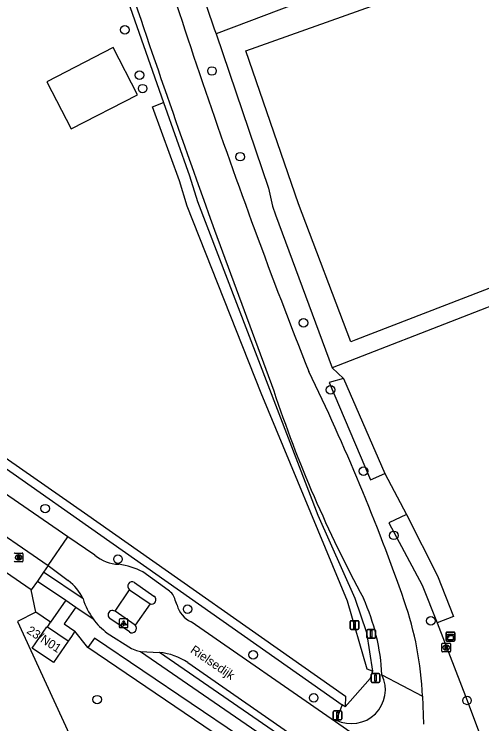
# Model space of a CAD drawing. Extents: x 163863 to 164644, y 379566 to 382155.
# Drawn here: x 164404.5 to 164457.9, y 381693.6 to 381774.7 of the extents above; entities that cross this region are included whole.
import ezdxf

# ---------------------------------------------------------------- set-up
doc = ezdxf.new("R2010")
doc.units = 0
for name, color, linetype in [('IMGEO_Afsluitpaal', 7, 'Continuous'), ('IMGEO_Boom', 7, 'Continuous'), ('IMGEO_Brandkraan', 7, 'Continuous'), ('IMGEO_Erf', 7, 'Continuous'), ('IMGEO_Grasland_agrarisch', 7, 'Continuous'), ('IMGEO_Groenvoorziening', 7, 'Continuous'), ('IMGEO_Hek', 7, 'Continuous'), ('IMGEO_Kast', 7, 'Continuous'), ('IMGEO_Lichtpunt', 7, 'Continuous'), ('IMGEO_Openbare_ruimte_label', 7, 'Continuous'), ('IMGEO_Pand', 7, 'Continuous'), ('IMGEO_Pand_nummerreeks', 7, 'Continuous'), ('IMGEO_Parkeervlak_open', 7, 'Continuous'), ('IMGEO_Rijbaan_lokaal_gesloten', 7, 'Continuous'), ('IMGEO_Rijbaan_lokaal_halfverhard', 7, 'Continuous'), ('IMGEO_Rijbaan_lokaal_open', 7, 'Continuous'), ('IMGEO_Rioolput', 7, 'Continuous'), ('IMGEO_Verkeersbordpaal', 7, 'Continuous'), ('IMGEO_Voetpad_open', 7, 'Continuous'), ('IMGEO_Waterloop', 7, 'Continuous')]:
    doc.layers.add(name, color=color, linetype=linetype)

msp = doc.modelspace()

# ---------------------------------------------------------------- linework, layer by layer
at = {"layer": 'IMGEO_Afsluitpaal'}
for p, q in [((164444.797, 381703.434), (164444.797, 381704.234)), ((164444.797, 381704.234), (164444.797, 381703.434)), ((164444.897, 381704.334), (164445.687, 381704.334)), ((164445.687, 381704.334), (164444.897, 381704.334)), ((164445.787, 381704.234), (164445.787, 381703.434)), ((164445.787, 381703.434), (164445.787, 381704.234)), ((164445.687, 381703.334), (164444.897, 381703.334)), ((164444.897, 381703.334), (164445.687, 381703.334)), ((164445.274, 381698.398), (164445.274, 381699.198)), ((164445.274, 381699.198), (164445.274, 381698.398)), ((164445.374, 381699.298), (164446.164, 381699.298)), ((164446.164, 381699.298), (164445.374, 381699.298)), ((164446.264, 381699.198), (164446.264, 381698.398)), ((164446.264, 381698.398), (164446.264, 381699.198)), ((164446.164, 381698.298), (164445.374, 381698.298)), ((164445.374, 381698.298), (164446.164, 381698.298)), ((164440.936, 381694.125), (164440.936, 381694.925)), ((164440.936, 381694.925), (164440.936, 381694.125)), ((164441.036, 381695.025), (164441.826, 381695.025)), ((164441.826, 381695.025), (164441.036, 381695.025)), ((164441.926, 381694.925), (164441.926, 381694.125)), ((164441.926, 381694.125), (164441.926, 381694.925)), ((164441.826, 381694.025), (164441.036, 381694.025)), ((164441.036, 381694.025), (164441.826, 381694.025))]:
    msp.add_line(p, q, dxfattribs=at)
for points in [[(164445.217, 381704.209), (164445.367, 381704.209), (164445.367, 381703.459), (164445.217, 381703.459), (164445.217, 381704.209)], [(164445.694, 381699.173), (164445.844, 381699.173), (164445.844, 381698.423), (164445.694, 381698.423), (164445.694, 381699.173)], [(164441.356, 381694.9), (164441.506, 381694.9), (164441.506, 381694.15), (164441.356, 381694.15), (164441.356, 381694.9)]]:
    msp.add_lwpolyline(points, dxfattribs=at)
for centre, start, end in [((164444.897, 381704.234), 90, 180), ((164444.897, 381704.234), 90, 180), ((164445.687, 381704.234), 0, 90), ((164445.687, 381704.234), 360, 90), ((164444.897, 381703.434), 180, 270), ((164444.897, 381703.434), 180, 270), ((164445.687, 381703.434), 270, 0), ((164445.687, 381703.434), 270, 0), ((164445.374, 381699.198), 90, 180), ((164445.374, 381699.198), 90, 180), ((164446.164, 381699.198), 0, 90), ((164446.164, 381699.198), 360, 90), ((164445.374, 381698.398), 180, 270), ((164445.374, 381698.398), 180, 270), ((164446.164, 381698.398), 270, 0), ((164446.164, 381698.398), 270, 0), ((164441.036, 381694.925), 90, 180), ((164441.036, 381694.925), 90, 180), ((164441.826, 381694.925), 0, 90), ((164441.826, 381694.925), 360, 90), ((164441.036, 381694.125), 180, 270), ((164441.036, 381694.125), 180, 270), ((164441.826, 381694.125), 270, 0), ((164441.826, 381694.125), 270, 0)]:
    msp.add_arc(centre, 0.1, start, end, dxfattribs=at)
at = {"layer": 'IMGEO_Boom'}
for centre in [(164417.112, 381772.922), (164418.805, 381767.744), (164427.081, 381768.213), (164419.153, 381766.193), (164430.293, 381758.411), (164437.543, 381739.415), (164440.63, 381731.745), (164444.404, 381722.448), (164407.999, 381718.165), (164447.885, 381715.108), (164416.332, 381712.377), (164424.297, 381706.667), (164452.106, 381705.325), (164431.799, 381701.437), (164413.958, 381696.321), (164438.709, 381696.515), (164456.242, 381696.233)]:
    msp.add_circle(centre, 0.489, dxfattribs=at)
at = {"layer": 'IMGEO_Brandkraan'}
for p, q in [((164404.539, 381713.084), (164405.391, 381713.084)), ((164405.465, 381713.01), (164405.465, 381712.158)), ((164404.975, 381712.304), (164404.95, 381712.304)), ((164404.952, 381712.864), (164404.977, 381712.864)), ((164405.391, 381712.084), (164404.539, 381712.084))]:
    msp.add_line(p, q, dxfattribs=at)
for points in [[(164404.539, 381713.084), (164405.391, 381713.084)], [(164405.465, 381713.01), (164405.465, 381712.158)], [(164404.812, 381712.784), (164404.812, 381712.384), (164405.025, 381712.384)], [(164405.043, 381712.784), (164404.812, 381712.784)], [(164404.991, 381712.703), (164404.937, 381712.703), (164404.937, 381712.627)], [(164404.937, 381712.627), (164404.99, 381712.627)], [(164404.999, 381712.551), (164404.937, 381712.551), (164404.937, 381712.47)], [(164404.937, 381712.47), (164404.999, 381712.47)], [(164405.391, 381712.084), (164404.539, 381712.084)]]:
    msp.add_lwpolyline(points, dxfattribs=at)
for centre, radius, start, end in [((164404.541, 381713.008), 0.0765, 91.55205, 178.44795), ((164404.541, 381713.008), 0.0765, 91.55205, 178.44795), ((164405.389, 381713.008), 0.0765, 1.55205, 88.44795), ((164405.389, 381713.008), 0.0765, 1.55205, 88.44795), ((164404.541, 381712.16), 0.0765, 181.55205, 268.44795), ((164404.541, 381712.16), 0.0765, 181.55205, 268.44795), ((164404.992, 381712.665), 0.0379, 267.82845, 90.93552), ((164405, 381712.51), 0.0404, 269.87594, 90.50774), ((164405.031, 381712.635), 0.251, 268.66757, 293.53466), ((164405.047, 381712.639), 0.145, 59.4692, 91.53667), ((164405.072, 381712.686), 0.0922, 285.51372, 58.15012), ((164405.077, 381712.494), 0.105, 301.31148, 78.98903), ((164405.389, 381712.16), 0.0765, 271.55205, 358.44795), ((164405.389, 381712.16), 0.0765, 271.55205, 358.44795)]:
    msp.add_arc(centre, radius, start, end, dxfattribs=at)
for centre, major_axis, ratio, start_param, end_param in [((164404.951, 381712.584), (-0.387, 0.002), 0.722429, 4.712389, 7.853982), ((164404.976, 381712.584), (-0.39, 0.002), 0.717154, 1.570796, 4.712389)]:
    msp.add_ellipse(centre, major_axis=major_axis, ratio=ratio, start_param=start_param, end_param=end_param, dxfattribs=at)
at = {"layer": 'IMGEO_Erf'}
msp.add_lwpolyline([(164580.013, 381810.414), (164581.346, 381805.246), (164575.754, 381802.969), (164541.615, 381789.068), (164545.187, 381772.796), (164538.087, 381770.586), (164534.647, 381771.115), (164468.83, 381745.172), (164457.1, 381740.602), (164440.833, 381734.263)], dxfattribs=at)
at = {"layer": 'IMGEO_Grasland_agrarisch'}
for points in [[(164600.098, 381839.014), (164585.232, 381833.12), (164548.829, 381818.751), (164518.638, 381806.884), (164490.643, 381796.474), (164469.448, 381788.316), (164427.546, 381772.442)], [(164443.539, 381737.474), (164442.939, 381737.247), (164436.966, 381753.014), (164430.965, 381770.512), (164456.78, 381779.759), (164478.348, 381787.868), (164505.546, 381798.321), (164526.662, 381806.514), (164530.385, 381805.09), (164531.541, 381804.475), (164532.487, 381803.404), (164538.297, 381784.937), (164539.439, 381780.675), (164539.19, 381777.888), (164537.822, 381775.597), (164535.89, 381774.091), (164533.834, 381772.761), (164490.018, 381755.433), (164443.539, 381737.474)], [(164418.253, 381799.855), (164427.349, 381773.022), (164427.546, 381772.442)]]:
    msp.add_lwpolyline(points, dxfattribs=at)
at = {"layer": 'IMGEO_Groenvoorziening'}
for points in [[(164416.201, 381779.849), (164421.545, 381764.607)], [(164427.546, 381772.442), (164433.526, 381754.803), (164433.997, 381752.734), (164434.331, 381751.745), (164440.833, 381734.263)], [(164440.833, 381734.263), (164442.117, 381733.052)], [(164446.861, 381722.173), (164449.308, 381717.487)], [(164406.925, 381706.323), (164406.418, 381708.86)], [(164406.925, 381706.323), (164404.83, 381705.266), (164418.395, 381675.757)], [(164408.629, 381705.166), (164406.925, 381706.323)], [(164452.839, 381705.104), (164456.242, 381696.233), (164460.508, 381684.892), (164470.413, 381677.426)], [(164412.893, 381702.27), (164411.398, 381704.132)], [(164445.453, 381699.564), (164445.182, 381698.732), (164442.313, 381695.498)], [(164441.971, 381695.738), (164441.297, 381693.99)]]:
    msp.add_lwpolyline(points, dxfattribs=at)
at = {"layer": 'IMGEO_Hek'}
for points in [[(164468.83, 381745.172), (164457.1, 381740.602)], [(164457.1, 381740.602), (164440.833, 381734.263)]]:
    msp.add_lwpolyline(points, dxfattribs=at)
at = {"layer": 'IMGEO_Kast'}
for p, q in [((164453.925, 381704.024), (164454.766, 381704.024)), ((164454.766, 381704.024), (164453.925, 381704.024)), ((164453.85, 381703.099), (164453.85, 381703.94)), ((164453.85, 381703.94), (164453.85, 381703.099)), ((164454.85, 381703.949), (164454.85, 381703.108)), ((164454.85, 381703.108), (164454.85, 381703.949)), ((164454.775, 381703.024), (164453.934, 381703.024)), ((164453.934, 381703.024), (164454.775, 381703.024))]:
    msp.add_line(p, q, dxfattribs=at)
for points in [[(164454.045, 381703.814), (164454.645, 381703.814), (164454.645, 381703.729), (164454.045, 381703.729), (164454.045, 381703.814)], [(164454.045, 381703.639), (164454.645, 381703.639), (164454.645, 381703.15), (164454.045, 381703.15), (164454.045, 381703.639)]]:
    msp.add_lwpolyline(points, dxfattribs=at)
msp.add_circle((164454.129, 381703.488), 0.0377, dxfattribs=at)
for centre, start, end in [((164453.928, 381703.946), 92.4484, 184.28452), ((164453.928, 381703.946), 92.4484, 184.28452), ((164454.772, 381703.946), 2.4484, 94.28452), ((164454.772, 381703.946), 2.4484, 94.28452), ((164453.928, 381703.102), 182.4484, 274.28452), ((164453.928, 381703.102), 182.4484, 274.28452), ((164454.772, 381703.102), 272.4484, 4.28452), ((164454.772, 381703.102), 272.4484, 4.28452)]:
    msp.add_arc(centre, 0.0779, start, end, dxfattribs=at)
at = {"layer": 'IMGEO_Lichtpunt'}
for p, q in [((164416.479, 381705.452), (164416.479, 381704.645)), ((164416.479, 381705.452), (164416.479, 381704.645)), ((164417.381, 381705.547), (164416.573, 381705.547)), ((164417.381, 381705.547), (164416.573, 381705.547)), ((164417.475, 381704.645), (164417.475, 381705.452)), ((164417.475, 381704.645), (164417.475, 381705.452)), ((164416.573, 381704.551), (164417.381, 381704.551)), ((164416.573, 381704.551), (164417.381, 381704.551))]:
    msp.add_line(p, q, dxfattribs=at)
for points in [[(164416.853, 381705.116), (164416.892, 381705.088), (164416.704, 381704.826), (164416.666, 381704.853), (164416.853, 381705.116)], [(164416.955, 381705.068), (164417.002, 381705.068), (164417.002, 381704.746), (164416.955, 381704.746), (164416.955, 381705.068)], [(164417.065, 381705.088), (164417.103, 381705.115), (164417.29, 381704.853), (164417.251, 381704.825), (164417.065, 381705.088)]]:
    msp.add_lwpolyline(points, dxfattribs=at)
msp.add_circle((164416.978, 381705.25), 0.0994, dxfattribs=at)
for centre, start, end in [((164416.573, 381705.452), 90, 180), ((164416.573, 381705.452), 90, 180), ((164417.381, 381705.452), 0, 90), ((164417.381, 381705.452), 0, 90), ((164416.573, 381704.645), 180, 270), ((164416.573, 381704.645), 180, 270), ((164417.381, 381704.645), 270, 0), ((164417.381, 381704.645), 270, 360)]:
    msp.add_arc(centre, 0.0946, start, end, dxfattribs=at)
at = {"layer": 'IMGEO_Pand'}
for points in [[(164408.191, 381766.99), (164410.97, 381761.583), (164418.566, 381765.488), (164415.787, 381770.894), (164408.191, 381766.99)], [(164410.636, 381702.998), (164408.971, 381700.556), (164406.531, 381702.22), (164408.196, 381704.662), (164408.255, 381704.621)], [(164410.636, 381702.998), (164408.255, 381704.621)]]:
    msp.add_lwpolyline(points, dxfattribs=at)
at = {"layer": 'IMGEO_Parkeervlak_open'}
for points in [[(164406.418, 381708.86), (164381.892, 381725.724), (164366.579, 381736.251)], [(164408.346, 381711.663), (164407.816, 381710.901)], [(164407.122, 381709.878), (164406.418, 381708.86)]]:
    msp.add_lwpolyline(points, dxfattribs=at)
at = {"layer": 'IMGEO_Rijbaan_lokaal_gesloten'}
for points in [[(164324.768, 381769.068), (164352.536, 381750), (164383.72, 381728.586), (164408.346, 381711.663)], [(164410.608, 381714.952), (164385.909, 381731.949), (164382.848, 381734.057)], [(164408.346, 381711.663), (164410.608, 381714.952)], [(164413.701, 381712.823), (164410.608, 381714.952)], [(164408.346, 381711.663), (164410.627, 381709.931)], [(164422.052, 381708.834), (164419.173, 381710.931)], [(164418.21, 381709.722), (164420.438, 381708.15)], [(164423.088, 381707.112), (164422.863, 381707.691)], [(164417.638, 381704.058), (164415.41, 381705.593)], [(164441.191, 381693.787), (164424.684, 381705.234)], [(164415.108, 381703.926), (164417.871, 381702.173), (164418.468, 381701.923), (164418.924, 381701.808)], [(164418.924, 381701.808), (164421.084, 381701.704)], [(164424.306, 381700.566), (164445.106, 381686.132)], [(164455.774, 381683.629), (164441.191, 381693.787)]]:
    msp.add_lwpolyline(points, dxfattribs=at)
for centre, radius, start, end in [((164416.629, 381716.454), 4.664, 231.11326, 267.44259), ((164415.29, 381703.367), 8.502, 62.8239, 82.35428), ((164407.619, 381705.714), 5.18, 24.37833, 54.497), ((164417.936, 381709.302), 0.501, 56.8492, 236.49953), ((164420.17, 381707.732), 0.497, 249.35691, 57.35736), ((164421.259, 381707.412), 1.628, 9.85687, 60.85729), ((164420.524, 381710.505), 8.606, 197.95255, 215.15765), ((164415.7, 381706.008), 0.506, 54.56794, 235.06763), ((164425.923, 381707.905), 2.944, 195.61576, 245.10268), ((164419.638, 381710.068), 7.632, 216.30636, 233.58763), ((164417.937, 381704.467), 0.507, 233.82818, 46.35763), ((164420.507, 381694.941), 6.788, 55.9678, 85.12609)]:
    msp.add_arc(centre, radius, start, end, dxfattribs=at)
at = {"layer": 'IMGEO_Rijbaan_lokaal_halfverhard'}
msp.add_lwpolyline([(164427.37, 381750), (164434.141, 381731.625)], dxfattribs=at)
for centre, radius, start, end in [((165106.27, 381998.229), 718.528, 197.518249, 200.210398), ((165706.499, 382210.947), 1359.648, 198.437671, 199.817128), ((165106.385, 381998.122), 718.598, 200.199284, 201.576641), ((164221.983, 381628.478), 240.478, 19.20953, 25.99054), ((164576.493, 381779.107), 150.062, 198.44616, 208.32428), ((164422.47, 381697.97), 24.074, 2.81472, 24.38158), ((164413.003, 381695.065), 38.185, 2.46924, 19.16559)]:
    msp.add_arc(centre, radius, start, end, dxfattribs=at)
at = {"layer": 'IMGEO_Rijbaan_lokaal_open'}
for points in [[(164415.993, 381706.42), (164417.659, 381708.884)], [(164417.659, 381708.884), (164419.995, 381707.267)], [(164419.995, 381707.267), (164418.287, 381704.834)], [(164418.287, 381704.834), (164415.993, 381706.42)], [(164446.515, 381699.152), (164451.153, 381696.71)], [(164451.153, 381696.71), (164451.272, 381693.533)], [(164441.297, 381693.99), (164441.191, 381693.787)]]:
    msp.add_lwpolyline(points, dxfattribs=at)
msp.add_arc((164443.036, 381697.45), 3.873, 243.31119, 26.07059, dxfattribs=at)
at = {"layer": 'IMGEO_Rioolput'}
for p, q in [((164453.363, 381701.847), (164453.363, 381702.699)), ((164453.438, 381702.773), (164454.29, 381702.773)), ((164453.851, 381702.553), (164453.876, 381702.553)), ((164454.364, 381702.699), (164454.364, 381701.847)), ((164454.29, 381701.773), (164453.438, 381701.773)), ((164453.874, 381701.993), (164453.849, 381701.993))]:
    msp.add_line(p, q, dxfattribs=at)
for points in [[(164453.363, 381701.847), (164453.363, 381702.699)], [(164453.438, 381702.773), (164454.29, 381702.773)], [(164453.952, 381702.471), (164453.7, 381702.473), (164453.7, 381702.073)], [(164453.878, 381702.392), (164453.824, 381702.392), (164453.824, 381702.311)], [(164454.364, 381702.699), (164454.364, 381701.847)], [(164454.29, 381701.773), (164453.438, 381701.773)], [(164453.7, 381702.073), (164453.824, 381702.073), (164453.824, 381702.235), (164453.835, 381702.235)], [(164453.824, 381702.311), (164453.876, 381702.311)], [(164453.882, 381702.206), (164453.953, 381702.073), (164454.093, 381702.073), (164454.028, 381702.199)]]:
    msp.add_lwpolyline(points, dxfattribs=at)
for centre, radius, start, end in [((164453.44, 381702.697), 0.0765, 91.55205, 178.44795), ((164453.44, 381702.697), 0.0765, 91.55205, 178.44795), ((164453.884, 381702.296), 0.0964, 77.00612, 93.18647), ((164453.898, 381702.353), 0.0378, 276.66336, 79.67722), ((164453.951, 381702.361), 0.109, 350.36119, 89.41601), ((164454.288, 381702.697), 0.0765, 1.55205, 88.44795), ((164454.288, 381702.697), 0.0765, 1.55205, 88.44795), ((164453.44, 381701.849), 0.0765, 181.55205, 268.44795), ((164453.44, 381701.849), 0.0765, 181.55205, 268.44795), ((164453.834, 381702.182), 0.0533, 26.02933, 88.69889), ((164453.86, 381702.5), 0.19, 274.7715, 282.96867), ((164453.949, 381702.361), 0.112, 277.58423, 350.98172), ((164453.933, 381702.146), 0.108, 29.51342, 73.79051), ((164454.288, 381701.849), 0.0765, 271.55205, 358.44795), ((164454.288, 381701.849), 0.0765, 271.55205, 358.44795)]:
    msp.add_arc(centre, radius, start, end, dxfattribs=at)
for centre, major_axis, ratio, start_param, end_param in [((164453.85, 381702.273), (-0.387, 0.002), 0.722429, 4.712389, 7.853982), ((164453.875, 381702.273), (-0.39, 0.002), 0.717154, 1.570796, 4.712389)]:
    msp.add_ellipse(centre, major_axis=major_axis, ratio=ratio, start_param=start_param, end_param=end_param, dxfattribs=at)
at = {"layer": 'IMGEO_Verkeersbordpaal'}
for p, q in [((164442.883, 381704.448), (164442.883, 381705.248)), ((164442.883, 381705.248), (164442.883, 381704.448)), ((164442.983, 381705.348), (164443.773, 381705.348)), ((164443.773, 381705.348), (164442.983, 381705.348)), ((164443.873, 381705.248), (164443.873, 381704.448)), ((164443.873, 381704.448), (164443.873, 381705.248)), ((164443.773, 381704.348), (164442.983, 381704.348)), ((164442.983, 381704.348), (164443.773, 381704.348))]:
    msp.add_line(p, q, dxfattribs=at)
msp.add_lwpolyline([(164443.303, 381705.223), (164443.453, 381705.223), (164443.453, 381704.473), (164443.303, 381704.473), (164443.303, 381705.223)], dxfattribs=at)
for centre, start, end in [((164442.983, 381705.248), 90, 180), ((164442.983, 381705.248), 90, 180), ((164443.773, 381705.248), 0, 90), ((164443.773, 381705.248), 360, 90), ((164442.983, 381704.448), 180, 270), ((164442.983, 381704.448), 180, 270), ((164443.773, 381704.448), 270, 0), ((164443.773, 381704.448), 270, 0)]:
    msp.add_arc(centre, 0.1, start, end, dxfattribs=at)
at = {"layer": 'IMGEO_Voetpad_open'}
for points in [[(164407.816, 381710.901), (164407.122, 381709.878)], [(164412.337, 381707.852), (164407.816, 381710.901)], [(164407.122, 381709.878), (164410.356, 381707.679)], [(164410.356, 381707.679), (164408.629, 381705.166)], [(164410.356, 381707.679), (164411.502, 381706.899)], [(164411.502, 381706.899), (164410.178, 381704.987), (164411.398, 381704.132)], [(164411.502, 381706.899), (164413.488, 381705.549)], [(164408.255, 381704.621), (164408.629, 381705.166)], [(164411.398, 381704.132), (164411.007, 381703.551), (164410.636, 381702.998)], [(164418.924, 381701.808), (164447.209, 381682.336)], [(164446.953, 381683.86), (164421.084, 381701.704)]]:
    msp.add_lwpolyline(points, dxfattribs=at)
at = {"layer": 'IMGEO_Waterloop'}
for points in [[(164445.453, 381699.564), (164444.814, 381699.801), (164442.562, 381707.597), (164432.716, 381731.373), (164424.257, 381752.745), (164423.35, 381755.66), (164420.288, 381764.098), (164421.545, 381764.607)], [(164421.545, 381764.607), (164424.509, 381756.221), (164425.411, 381753.268), (164439.193, 381717.401), (164443.41, 381707.913), (164444.739, 381704.016), (164445.453, 381699.564)], [(164384.279, 381736.27), (164384.767, 381737.008), (164412.499, 381717.701), (164442.345, 381696.707), (164442.313, 381695.498)], [(164384.279, 381736.27), (164411.916, 381716.853), (164441.971, 381695.738)], [(164442.117, 381733.052), (164440.48, 381732.584), (164445.218, 381721.442), (164446.861, 381722.173)], [(164442.117, 381733.052), (164446.861, 381722.173)], [(164449.308, 381717.487), (164447.311, 381716.527), (164451.098, 381709.418), (164452.839, 381705.104)], [(164449.308, 381717.487), (164452.858, 381710.476), (164454.684, 381705.828), (164452.839, 381705.104)], [(164429.462, 381691.018), (164430.229, 381692.16), (164413.634, 381703.357), (164412.893, 381702.27)], [(164429.462, 381691.018), (164412.893, 381702.27)], [(164442.313, 381695.498), (164441.971, 381695.738)]]:
    msp.add_lwpolyline(points, dxfattribs=at)

# ---------------------------------------------------------------- texts
at = {"layer": 'IMGEO_Openbare_ruimte_label'}
msp.add_text('Rielsedijk', height=1, rotation=325.59477, dxfattribs=at).set_placement((164424.523, 381701.784))
at = {"layer": 'IMGEO_Pand_nummerreeks'}
msp.add_text('23/N01', height=1, rotation=327.02959, dxfattribs=at).set_placement((164405.813, 381703.982))

doc.saveas('drawing.dxf')
